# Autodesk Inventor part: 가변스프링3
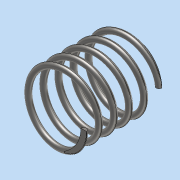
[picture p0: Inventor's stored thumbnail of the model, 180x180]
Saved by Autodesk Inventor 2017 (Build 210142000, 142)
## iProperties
Part Number: 가변스프링3
Material: 강철, 연강
Document SubType Name: Modeling
Designer: MRC
Density: 7.85 g/cm^3
Appearance: 반연마
Mass: 8.3874 g
Surface Area: 21.6623 cm^2
Volume: 1.06846 cm^3
Author: MRC
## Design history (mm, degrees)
sketch "스케치1"
  geometry: L1 (0, 0)-(0, 26.358); L2 (0, 0)-(11, 0); L3 (0, 26.358)-(11, 26.358); C1 r 1 at (11, 0)
  constraints: 6 end point, 2 horizontal, 1 centre point, 1 coincident, 1 vertical
  dimensions: "d0" = 26.35829 distance of L1.start L1.end (derived); "d1" = 11 distance of L1.end L3.end; "d2" = 11 distance of L1.start L2.end; "d3" = 2 diameter of C1
feature "코일1" sketch "스케치1" pitch "d4" = 10; turns "d6" = 5; dims "d5" = 26.35831 (computed from d0), "d7" = 0, angle "d8" = 90 deg, angle "d9" = 90 deg, "d10" = 0, "d11" = 0
sketch "스케치2"
  geometry: L1 (26.358, 15)-(0, 15); L2 (0, 15)-(0, -15); L3 (0, -15)-(26.358, -15); L4 (26.358, -15)-(26.358, 15); 2 further points
  constraints: 8 end point, 2 parallel, 1 coincident, 1 horizontal, 1 midpoint, 1 perpendicular
  dimensions: "d12" = 26.35831 distance of L2.end L3.end (computed from d0); "d13" = 30 distance of L3.end L1.start
extrude "돌출1" sketch "스케치2" stored distance "d14" = 0; taper "d15" = 0 deg
node "솔리드1"
